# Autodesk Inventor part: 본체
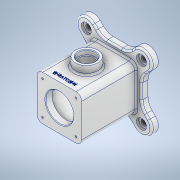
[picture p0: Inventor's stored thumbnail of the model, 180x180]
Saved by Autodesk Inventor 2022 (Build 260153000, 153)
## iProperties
Created: 2022-05
Part Number: 본체
Material: 알루미늄 6061
Document SubType Name: Modeling
Designer: Admin
Mass: 1076.28 g
Surface Area: 879.96 cm^2
Volume: 398.62 cm^3
Density: 2.7 g/cm^3
Appearance: 알루미늄 - 평지
Author: Admin
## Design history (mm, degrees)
sketch "스케치1"
  geometry: L1 (-40, -40)-(40, -40); L2 (40, -40)-(40, 40); L3 (40, 40)-(-40, 40); L4 (-40, 40)-(-40, -40); L5 (-40, -40)-(40, 40); L6 (40, -40)-(-40, 40); 1 further point
  constraints: 12 end point, 2 midpoint, 2 parallel, 1 horizontal, 1 perpendicular
  dimensions: "d0" = 80 distance of L3.end L2.end; "d1" = 80 distance of L2.end L1.end
extrude "돌출1" new body sketch "스케치1" stored distance "d2" = 98; taper "d3" = 0 deg
sketch "스케치2"
  geometry: L1 (-49, 49)-(49, 49); L2 (49, 49)-(49, -49); L3 (49, -49)-(-49, -49); L4 (-49, -49)-(-49, 49); L5 (-49, 49)-(49, -49); L6 (49, 49)-(-49, -49); L7 (-49.497, 49.497)-(-12.728, 12.728); L8 (-62.225, 36.77)-(-25.456, 0); L9 (0, 25.456)-(-36.77, 62.225); L10 (49.497, 49.497)-(12.728, 12.728); L11 (36.77, 62.225)-(0, 25.456); L12 (25.456, 0)-(62.225, 36.77); L13 (49.497, -49.497)-(12.728, -12.728); L14 (62.225, -36.77)-(25.456, 0); L15 (0, -25.456)-(36.77, -62.225); L16 (-49.497, -49.497)-(-12.728, -12.728); L17 (-36.77, -62.225)-(0, -25.456); L18 (-25.456, 0)-(-62.225, -36.77); A1 r 70 centre (0, 0) between (-49.497, 49.497) and (49.497, 49.497); A2 r 18 centre (-49.497, 49.497) between (-36.77, 62.225) and (-62.225, 36.77); A3 r 18 centre (-12.728, 12.728) between (-25.456, 0) and (0, 25.456); A4 r 18 centre (49.497, 49.497) between (62.225, 36.77) and (36.77, 62.225); A5 r 18 centre (12.728, 12.728) between (0, 25.456) and (25.456, 0); A6 r 18 centre (49.497, -49.497) between (36.77, -62.225) and (62.225, -36.77); A7 r 18 centre (12.728, -12.728) between (25.456, 0) and (0, -25.456); A8 r 18 centre (-49.497, -49.497) between (-62.225, -36.77) and (-36.77, -62.225); A9 r 18 centre (-12.728, -12.728) between (0, -25.456) and (-25.456, 0); 15 further points
  constraints: 44 end point, 24 point on circle, 16 tangent, 9 centre point, 8 midpoint, 7 point on line, 6 parallel, 1 coincident, 1 horizontal, 1 perpendicular
  dimensions: "d4" = 98 distance of L2.end L3.end; "d5" = 98 distance of L1.end L2.end; "d6" = 140 diameter of A1; "d7" = 36 distance between parallel lines of L8 L9; "d8" = 36 distance between parallel lines of L12 L11; "d9" = 36 distance between parallel lines of L15 L14; "d10" = 36 distance between parallel lines of L17 L18
extrude "돌출2" join sketch "스케치2" distance "d11" = 12; taper "d12" = 0 deg
sketch "스케치5"
  geometry: L1 (-94.496, 0)-(94.496, 0) reference; L2 (0, -83)-(0, 71) reference; L3 (0, 0)-(55, 0); L4 (55, 0)-(55, -20); L5 (55, -20)-(0, -20); L6 (0, -20)-(0, 0); 1 further point
  constraints: 8 end point, 2 parallel, 1 horizontal, 1 midpoint, 1 perpendicular, 1 point on line
  dimensions: "d20" = 40 diameter of L5 L1; "d21" = 55 distance between parallel lines of L2 L4
revolve "회전2" sketch "스케치5" stored, may be unused: angle "d22" = 90 deg
sketch "스케치3"
  geometry: L1 (0, -83)-(0, 71) reference; L2 (-94.496, 0)-(94.496, 0) reference; L3 (25, 49)-(0, 49); L4 (0, 49)-(0, 37); L5 (0, 37)-(25, 37); L6 (25, 37)-(25, 49); L7 (0, 37)-(35, 37); L8 (35, 37)-(35, -49); L9 (35, -49)-(0, -49); L10 (0, -49)-(0, 37); L11 (0, -49)-(25, -49); L12 (25, -49)-(25, -61); L13 (25, -61)-(0, -61); L14 (0, -61)-(0, -49); L15 (-23.544, -61)-(23.544, -61) reference; L16 (40, 49)-(-40, 49) reference; 3 further points
  constraints: 24 end point, 6 parallel, 3 horizontal, 3 perpendicular, 2 midpoint, 1 point on line
  dimensions: "d13" = 50 diameter of L6 L1; "d14" = 50 diameter of L12 L1; "d15" = 70 diameter of L8 L1; "d16" = 12 distance of L5.end L3.start; "d17" = 12 distance of L11.end L12.end
revolve "회전1" sketch "스케치3" stored, may be unused: angle "d18" = 90 deg
sketch "스케치6"
  geometry: C1 r 15 at (0, 0); 1 further point
  constraints: 1 centre point, 1 coincident
  dimensions: "d23" = 30 diameter of C1
extrude "돌출3" cut sketch "스케치6" distance "d24" = 8; taper "d25" = 0 deg
sketch "스케치7"
  geometry: C1 r 12.5 at (0, 0); 1 further point
  constraints: 1 centre point, 1 coincident
  dimensions: "d26" = 25 diameter of C1
extrude "돌출4" cut sketch "스케치7" stored distance "d27" = 8; taper "d28" = 0 deg
sketch "스케치8"
  geometry: L1 (-30, -30)-(30, -30); L2 (30, -30)-(30, 30); L3 (30, 30)-(-30, 30); L4 (-30, 30)-(-30, -30); L5 (-30, -30)-(30, 30); L6 (30, -30)-(-30, 30); 5 further points
  constraints: 12 end point, 4 coincident, 2 midpoint, 2 parallel, 1 horizontal, 1 perpendicular
  dimensions: "d29" = 60 distance of L3.end L2.end; "d30" = 60 distance of L2.end L1.end
hole "구멍1" sketch "스케치8" at (-30, 30), (30, 30), (30, -30), (-30, -30) diameter "d31" = 3.242; stored, may be unused: countersink angle "d35" = 90 deg, drill point angle "d37" = 118 deg; dims "d32" = 8, "d33" = 4, "d34" = 2, "d36" = 10
sketch "스케치9"
  geometry: L1 (-30, -30)-(30, -30); L2 (30, -30)-(30, 30); L3 (30, 30)-(-30, 30); L4 (-30, 30)-(-30, -30); L5 (-30, -30)-(30, 30); L6 (30, -30)-(-30, 30); 5 further points
  constraints: 12 end point, 4 coincident, 2 midpoint, 2 parallel, 1 horizontal, 1 perpendicular
  dimensions: "d38" = 60 distance of L3.end L2.end; "d39" = 60 distance of L2.end L1.end
hole "구멍2" sketch "스케치9" at (-30, 30), (30, 30), (30, -30), (-30, -30) diameter "d40" = 3.242; stored, may be unused: countersink angle "d44" = 90 deg, drill point angle "d46" = 118 deg; dims "d41" = 8, "d42" = 4, "d43" = 2, "d45" = 10
sketch "스케치10"
  geometry: C1 r 70 at (0, 0); A1 r 18 centre (-49.497, 49.497) between (-36.77, 62.225) and (-62.225, 36.77) reference; A2 r 18 centre (49.497, 49.497) between (62.225, 36.77) and (36.77, 62.225) reference; A3 r 18 centre (49.497, -49.497) between (36.77, -62.225) and (62.225, -36.77) reference; A4 r 18 centre (-49.497, -49.497) between (-62.225, -36.77) and (-36.77, -62.225) reference; 5 further points
  constraints: 5 coincident, 1 centre point
  dimensions: "d47" = 140 diameter of C1
hole "구멍3" sketch "스케치10" at (-49.497, 49.497), (49.497, 49.497), (49.497, -49.497), (-49.497, -49.497) diameter "d48" = 10; stored, may be unused: countersink angle "d52" = 90 deg, drill point angle "d54" = 0 deg; dims "d49" = 8, "d50" = 18, "d51" = 4, "d53" = 12
sketch "스케치11"
  geometry: L1 (80, 0)-(0, 0) reference; L2 (40, 132)-(40, -22) reference; 2 further points
  constraints: 1 point on line, 1 other
  dimensions: "d55" = 10 distance from line of L1 point (40, 10)
feature "엠보싱1" sketch "스케치11" dims "d0" = 80, "d1" = 80, "d56" = 0.5, "d57" = 0
fillet "모깎기1" dims "d58" = 10
chamfer "모따기1" distance "d59" = 1; stored, may be unused: second distance "d60" = 2, angle "d61" = 45 deg
fillet "모깎기2" dims "d62" = 25
fillet "모깎기3" dims "d63" = 3
node "솔리드1"
feature "A9D066F2-1C7D-4E18-AEED-F7BC21143FA4" dims "d48" = 10, "d49" = 8, "d50" = 18, "d51" = 4, "d52" = 90 deg, "d53" = 12, "d54" = 0
